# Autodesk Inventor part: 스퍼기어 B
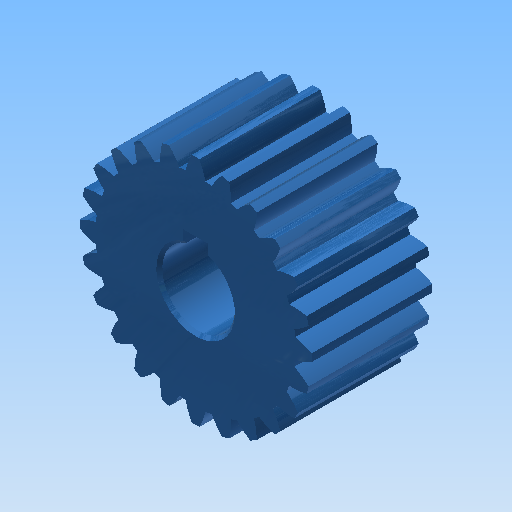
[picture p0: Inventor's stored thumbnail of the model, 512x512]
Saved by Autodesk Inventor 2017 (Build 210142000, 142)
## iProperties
Created: 2020-04
Part Number: 스퍼기어 B
Material: Steel
Document SubType Name: Modeling
Designer: mduedu
Categories: <?xml version="1.0" encoding="UTF-16"?> <MemberInstance><Categories><FamilyTemplate><FamilyTemplateParameter ValueType="xs:double" Id="1" ObjectReferenceKey="da
Density: 7.85 g/cm^3
Mass: 140.141 g
Surface Area: 65.0479 cm^2
Volume: 17.8524 cm^3
Appearance: 청록색
CustomPartVersion: 1
Author: mduedu
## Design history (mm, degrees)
sketch "Sketch1"
  geometry: C1 r 19.2 at (0, 0)
  constraints: 1 centre point
  dimensions: "d0" = 38.4 diameter of C1 (= da_da)
extrude "Extrusion1" new body sketch "Sketch1" distance "d1" = 20 (= da_b); taper "d2" = 0 deg
workplane "Work Plane2"
sketch "Sketch2"
  geometry: C1 r 19.2 at (0, 0) reference; C2 r 18 at (0, 0)
  constraints: 1 centre point, 1 coincident
  dimensions: "d3" = 36 diameter of C2 (= da_dw)
feature "피치 지름" sketch "Sketch2" dims "d4" = 10, "d5" = 0
workplane "Work Plane8"
workplane "Work Plane9"
feature "스퍼 기어" dims "da_b" = 20, "da_d" = 36, "da_aw" = 45, "da_da" = 38.4, "da_df" = 33.129, "da_dw" = 36, angle "da_beta" = 0 deg, "da_lefttooth" = 0, "da_righttooth" = 0
sketch "스케치3"
  geometry: L1 (-2, 5.657)-(2, 5.657); L2 (2, 5.657)-(2, 7.8); L3 (2, 7.8)-(-2, 7.8); L4 (-2, 7.8)-(-2, 5.657); A1 r 6 centre (0, 0) between (-2, 5.657) and (2, 5.657); 1 further point
  constraints: 8 end point, 2 parallel, 2 point on circle, 1 centre point, 1 coincident, 1 horizontal, 1 perpendicular
  dimensions: "d49" = 12 diameter of A1; "d51" = 4 distance of L2.end L3.end; "d52" = 13.8 dimension on A1 L3
extrude "돌출2" cut sketch "스케치3" stored distance "d53" = 10; taper "d54" = 0 deg
chamfer "모따기1" distance "d55" = 0.5; stored, may be unused: second distance "d56" = 2, angle "d57" = 45 deg
body "Solid1"
body "Srf1"
other parameters: "d16" = 45 (= da_aw), "d17" = 0, "d34" = 7.5 deg (computed from da_z), "d39" = 0, "d41" = 0, "d43" = 45 (= da_aw), "d46" = 45 (= da_aw), "d47" = 0, "d48" = 0
